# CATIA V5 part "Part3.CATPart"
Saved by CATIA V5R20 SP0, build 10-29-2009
Part number: 大齿轮
Bounding box of the stored display mesh (mm): x -4 to -1, y 9.032 to 40.968, z -16 to 16
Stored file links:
  D:\CATIA Data\Part3.CATPart
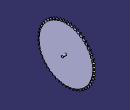
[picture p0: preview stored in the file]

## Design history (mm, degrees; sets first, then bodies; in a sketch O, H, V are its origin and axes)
Body1 (main body)
  Plane1: type Offset, RefPlane yz-plane, Offset 4, reversed
  Sketch1 on Plane1, origin (-4, 0, 0), H (0, 1, 0), V (0, 0, 1)
    circle A1 centre (25, 0) radius 15
    point P1 (25, 0)
    radius A1 = 15
    distance P1 V = 25
    coincidence: P1 H
  Pad1: profile Sketch1, direction (1, 0, 0), length 1
  Sketch2 on Plane1, origin (-4, 0, 0), H (0, 1, 0), V (0, 0, 1)
    axis line L1 (25, 16) -> (25, -16)
    point P1 (25, 16)
    arc A1 centre (25, 0) radius 15 from (25.31, 14.9968) to (24.69, 14.9968) ccw
    point P3 (25, 0)
    line L2 (25.31, 14.9968) -> (25, 16)
    line L3 (25, 16) -> (24.69, 14.9968)
    distance V L1 = 25
    radius A1 = 15
    distance P1 H = 16
    length L3 = 1.05
    length L2 = 1.05
    vertical: L1 V
    midpoint: P3 L1
    coincidence: P3 L1
    fix: P3, L1
  Pad2: profile Sketch2, direction (1, 0, 0), length 1
  Plane2: type Offset, RefPlane zx-plane, Offset 25
  Sketch3 on Plane2, origin (0, 25, 0), H (-1, 0, 0), V (0, 0, 1)
    line L1 (-10, 0) -> (20, 0)
    point P1 (-10, 0)
    coincidence: P1 H
    horizontal: L1 H
  CircPattern1: of Pad2, instances 50, angular step 7.2, axis from Sketch3.L1
  Sketch4 on face of CircPattern1, origin (-3, 0, 0), H (0, 1, 0), V (0, 0, 1)
    circle A1 centre (25, 0) radius 0.6
    point P1 (25, 0)
    radius A1 = 0.6
    distance P1 V = 25
    coincidence: P1 H
  Pad3: profile Sketch4, direction (1, 0, 0), length 2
